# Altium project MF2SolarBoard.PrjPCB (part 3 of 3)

## Sheet Peripherals.SchDoc
size B; SheetNumber: 11; nhSheetName: Digital Peripherals
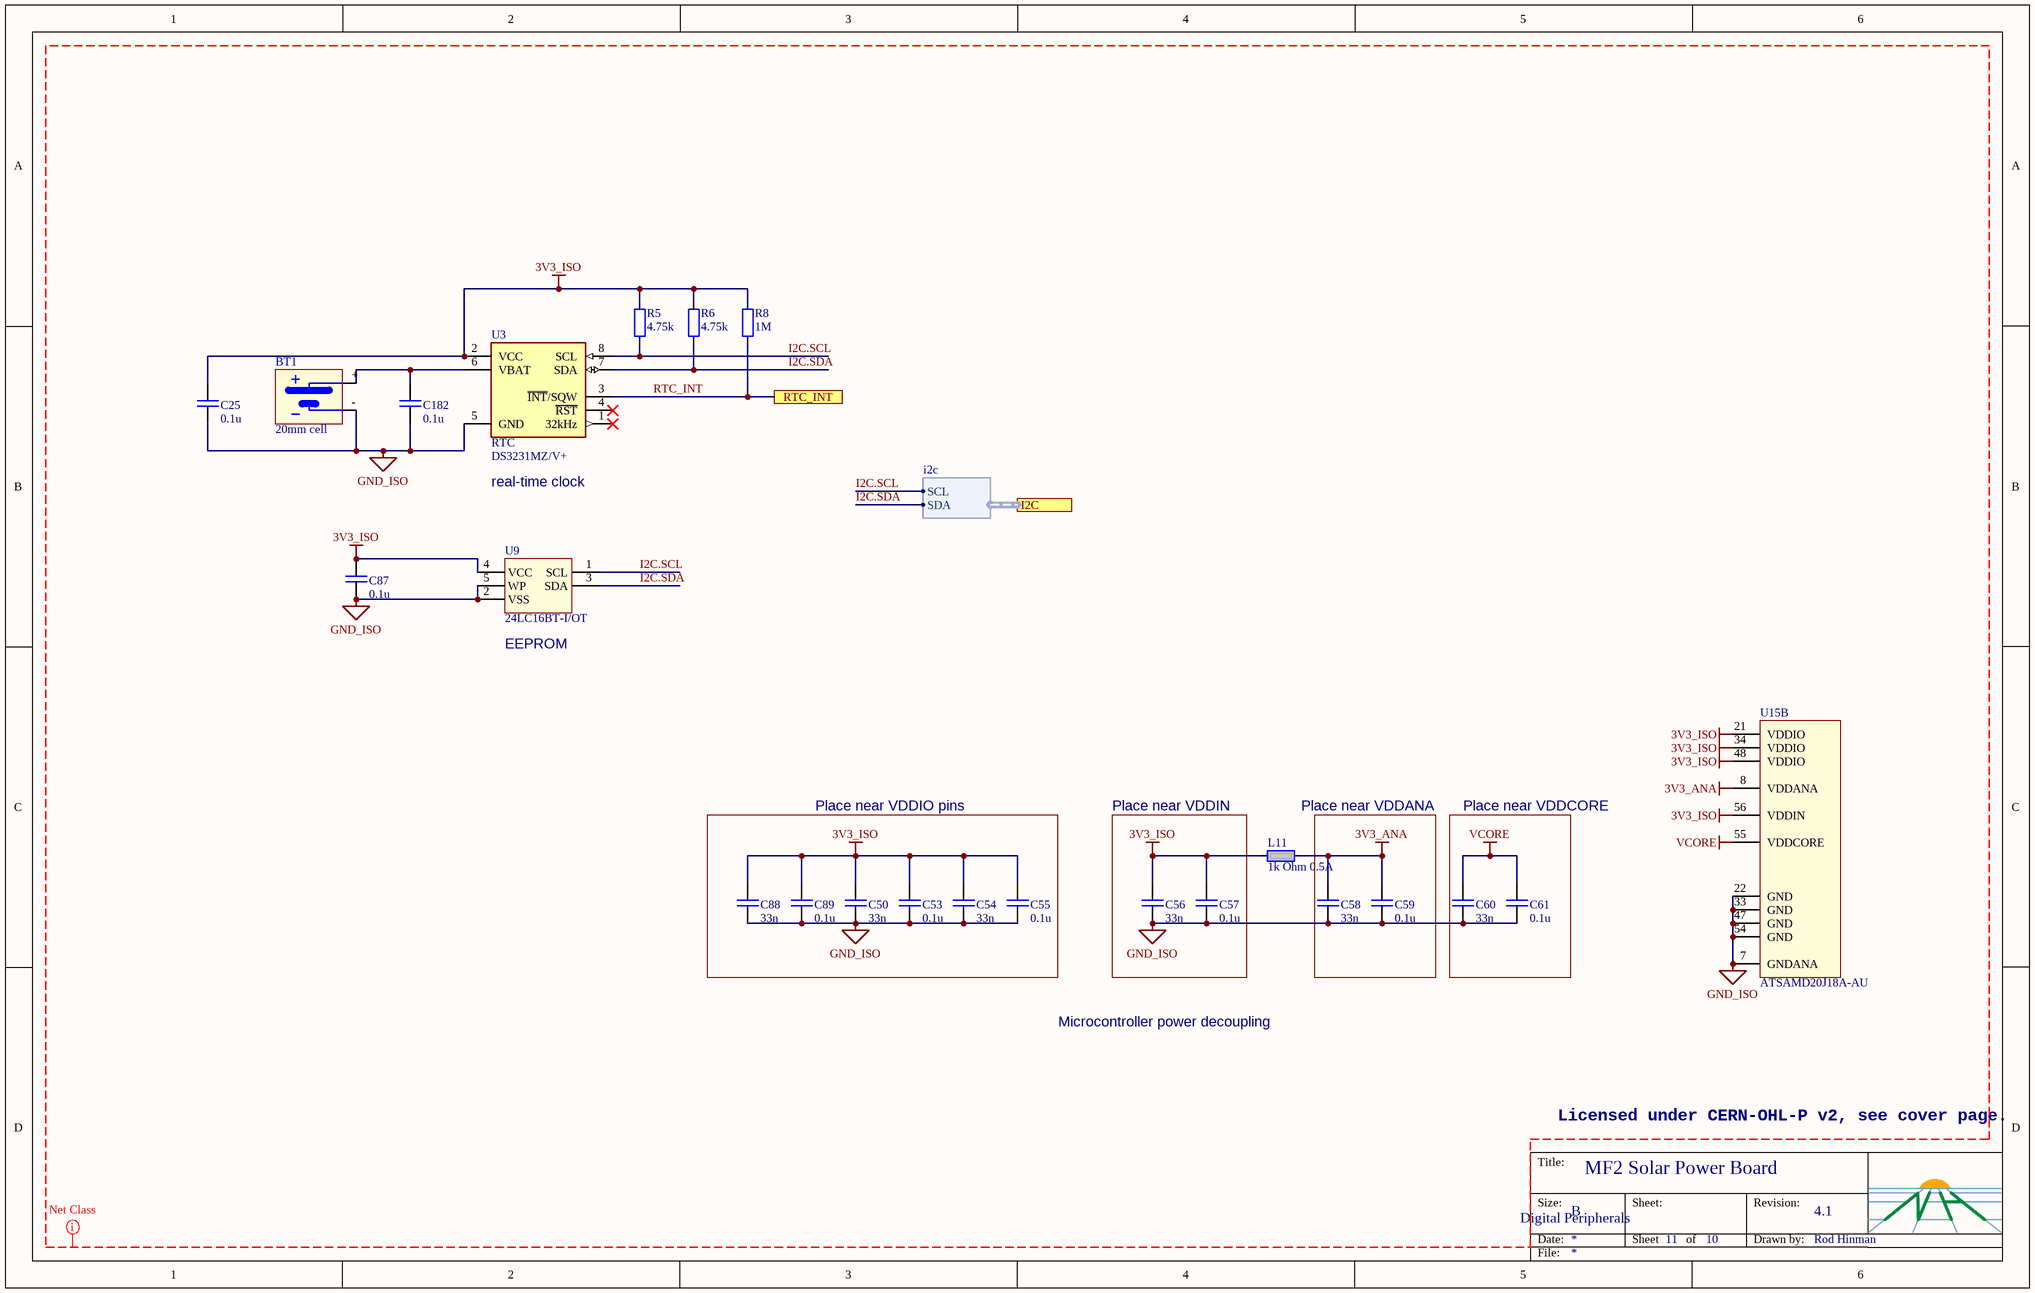
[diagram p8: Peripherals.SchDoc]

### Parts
BT1  20mm cell  [HARWIN_S8401-46]
C25  value_text: 0.1u  [CAPC1608X09N[0603]]  (hidden comment: 50V X7R 0603)
C50  value_text: 33n  [CAPC1608X09N[0603]]  (hidden comment: 50V X7R 0603)
C53  value_text: 0.1u  [CAPC1608X09N[0603]]  (hidden comment: 50V X7R 0603)
C54  value_text: 33n  [CAPC1608X09N[0603]]  (hidden comment: 50V X7R 0603)
C55  value_text: 0.1u  [CAPC1608X09N[0603]]  (hidden comment: 50V X7R 0603)
C56  value_text: 33n  [CAPC1608X09N[0603]]  (hidden comment: 50V X7R 0603)
C57  value_text: 0.1u  [CAPC1608X09N[0603]]  (hidden comment: 50V X7R 0603)
C58  value_text: 33n  [CAPC1608X09N[0603]]  (hidden comment: 50V X7R 0603)
C59  value_text: 0.1u  [CAPC1608X09N[0603]]  (hidden comment: 50V X7R 0603)
C60  value_text: 33n  [CAPC1608X09N[0603]]  (hidden comment: 50V X7R 0603)
C61  value_text: 0.1u  [CAPC1608X09N[0603]]  (hidden comment: 50V X7R 0603)
C87  value_text: 0.1u  [CAPC1608X09N[0603]]  (hidden comment: 50V X7R 0603)
C88  value_text: 33n  [CAPC1608X09N[0603]]  (hidden comment: 50V X7R 0603)
C89  value_text: 0.1u  [CAPC1608X09N[0603]]  (hidden comment: 50V X7R 0603)
C182  value_text: 0.1u  [CAPC1608X09N[0603]]  (hidden comment: 50V X7R 0603)
L11  1k Ohm 0.5A  [INDC2012X110N[0805]]
R5  value_text: 4.75k  [RESC1608X05AN[0603]]  (hidden comment: 1/10W 0603 1%)
R6  value_text: 4.75k  [RESC1608X05AN[0603]]  (hidden comment: 1/10W 0603 1%)
R8  value_text: 1M  [RESC1608X05AN[0603]]  (hidden comment: 1/10W 0603 1%)
U3  RTC  [SOIC127P600X170-8N]
U9  manufacturer_pn: 24LC16BT-I/OT  [SOT-23-5_MC]  (hidden comment: 16kbit I2C)
U15  manufacturer_pn: ATSAMD20J18A-AU  [ATM-TQFP64]  (hidden comment: 48MHz 256k 32k)  (part B of 2)

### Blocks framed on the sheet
Place near VDDIO pins: C50 C53-C55 C88 C89
Place near VDDIN: C56 C57
Place near VDDCORE: C60 C61

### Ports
I2C (harness i2c), RTC_INT

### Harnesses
i2c: SDA, SCL

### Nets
3V3_ANA: C58.1 C59.1 L11.2 U15.8(VDDANA)
3V3_ISO: C25.1 C50.1 C53.1 C54.1 C55.1 C56.1 C57.1 C87.1 C88.1 C89.1 L11.1 R5.2 R6.2 R8.2 U3.2(VCC) U9.4(VCC) U15.21(VDDIO) U15.34(VDDIO) U15.48(VDDIO) U15.56(VDDIN)
GND_ISO: BT1.- C25.2 C50.2 C53.2 C54.2 C55.2 C56.2 C57.2 C58.2 C59.2 C60.2 C61.2 C87.2 C88.2 C89.2 C182.2 U3.5(GND) U9.2(VSS) U9.5(WP) U15.7(GNDANA) U15.22(GND) U15.33(GND) U15.47(GND) U15.54(GND)
VCORE: C60.1 C61.1 U15.55(VDDCORE)
I2C.SCL: R5.1 U3.8(SCL) U9.1(SCL) ; port I2C.SCL
I2C.SDA: R6.1 U3.7(SDA) U9.3(SDA) ; port I2C.SDA
RTC_INT: R8.1 U3.3(~{INT}/SQW) ; port RTC_INT
NetBT1_+: BT1.+ C182.1 U3.6(VBAT)

Not connected (* = marked no-connect by the designer): U3 1(32kHz)* 4(~{RST})*

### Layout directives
net class SELV: 3V3_ANA, 3V3_ISO, GND_ISO, I2C.SCL, I2C.SDA, RTC_INT, VCORE

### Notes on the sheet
- real-time clock
- (near U9) EEPROM
- (near L11) Place near VDDANA
- Microcontroller power decoupling
- Licensed under CERN-OHL-P v2, see cover page.

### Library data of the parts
BT1 = CONN-00070: HOLDER BATT COIN CR2032/20MM; manufacturer: Harwin Inc.; manufacturer_pn: S8401-46; id: 140463
C25 C53 C55 C57 C59 C61 C87 C89 C182 = CAP-00001: 0.10µF 50V Ceramic Capacitor X7R 0603 (1608 Metric) 0.063" L x 0.031" W (1.60mm x 0.80mm); manufacturer: Murata Electronics North America; manufacturer_pn: GRM188R71H104KA93D; id: 136482; value: 1E-7; Key Parameters: V >= 25V
C50 C54 C56 C58 C60 C88 = CAP-00000: 0.033µF 50V Ceramic Capacitor X7R 0603 (1608 Metric) 0.063" L x 0.031" W (1.60mm x 0.80mm); manufacturer: Murata Electronics North America; manufacturer_pn: GRM188R71H333KA61D; id: 136460; value: 3.3E-8; Key Parameters: V >= 16V
L11 = FER-00005: FERRITE BEAD 1 KOHM 0805 1LN 0.28 ohm; manufacturer: Murata Electronics North America; manufacturer_pn: BLM21AG102SN1D; id: 137114; value: 1000
R5 R6 = RES-00013: RES SMD 4.75K OHM 1% 1/10W 0603; manufacturer: Panasonic Electronic Components; manufacturer_pn: ERJ-3EKF4751V; id: 137091; value: 4750; Key Parameters: 5% OK
R8 = RES-00114: 1 MOhms ±1% 0.1W, 1/10W Chip Resistor 0603 (1608 Metric) Automotive AEC-Q200 Thick Film; manufacturer: Panasonic Electronic Components; manufacturer_pn: ERJ-3EKF1004V; id: 185423; value: 1000000; Key Parameters: 5% OK
U3 = ICDIG-00002: Real Time Clock (RTC) IC Clock/Calendar I²C, 2-Wire Serial 8-SOIC (0.154in 3.90mm Width); manufacturer: Maxim Integrated; id: 137384
U9 = ICDIG-00007: EEPROM Memory IC 16Kb (2K x 8) I²C 900ns SOT-23-5; manufacturer: Microchip Technology; id: 169358
U15 = MCU-00010: ARM® Cortex®-M0+ SAM D20J Microcontroller IC 32-Bit 48MHz 256KB (256K x 8) FLASH 64-LQFP (10x10); manufacturer: Atmel; id: 169288

## Sheet HVAuxOutput.SchDoc
size B; SheetNumber: 8; nhSheetName: HV Auxiliary Output
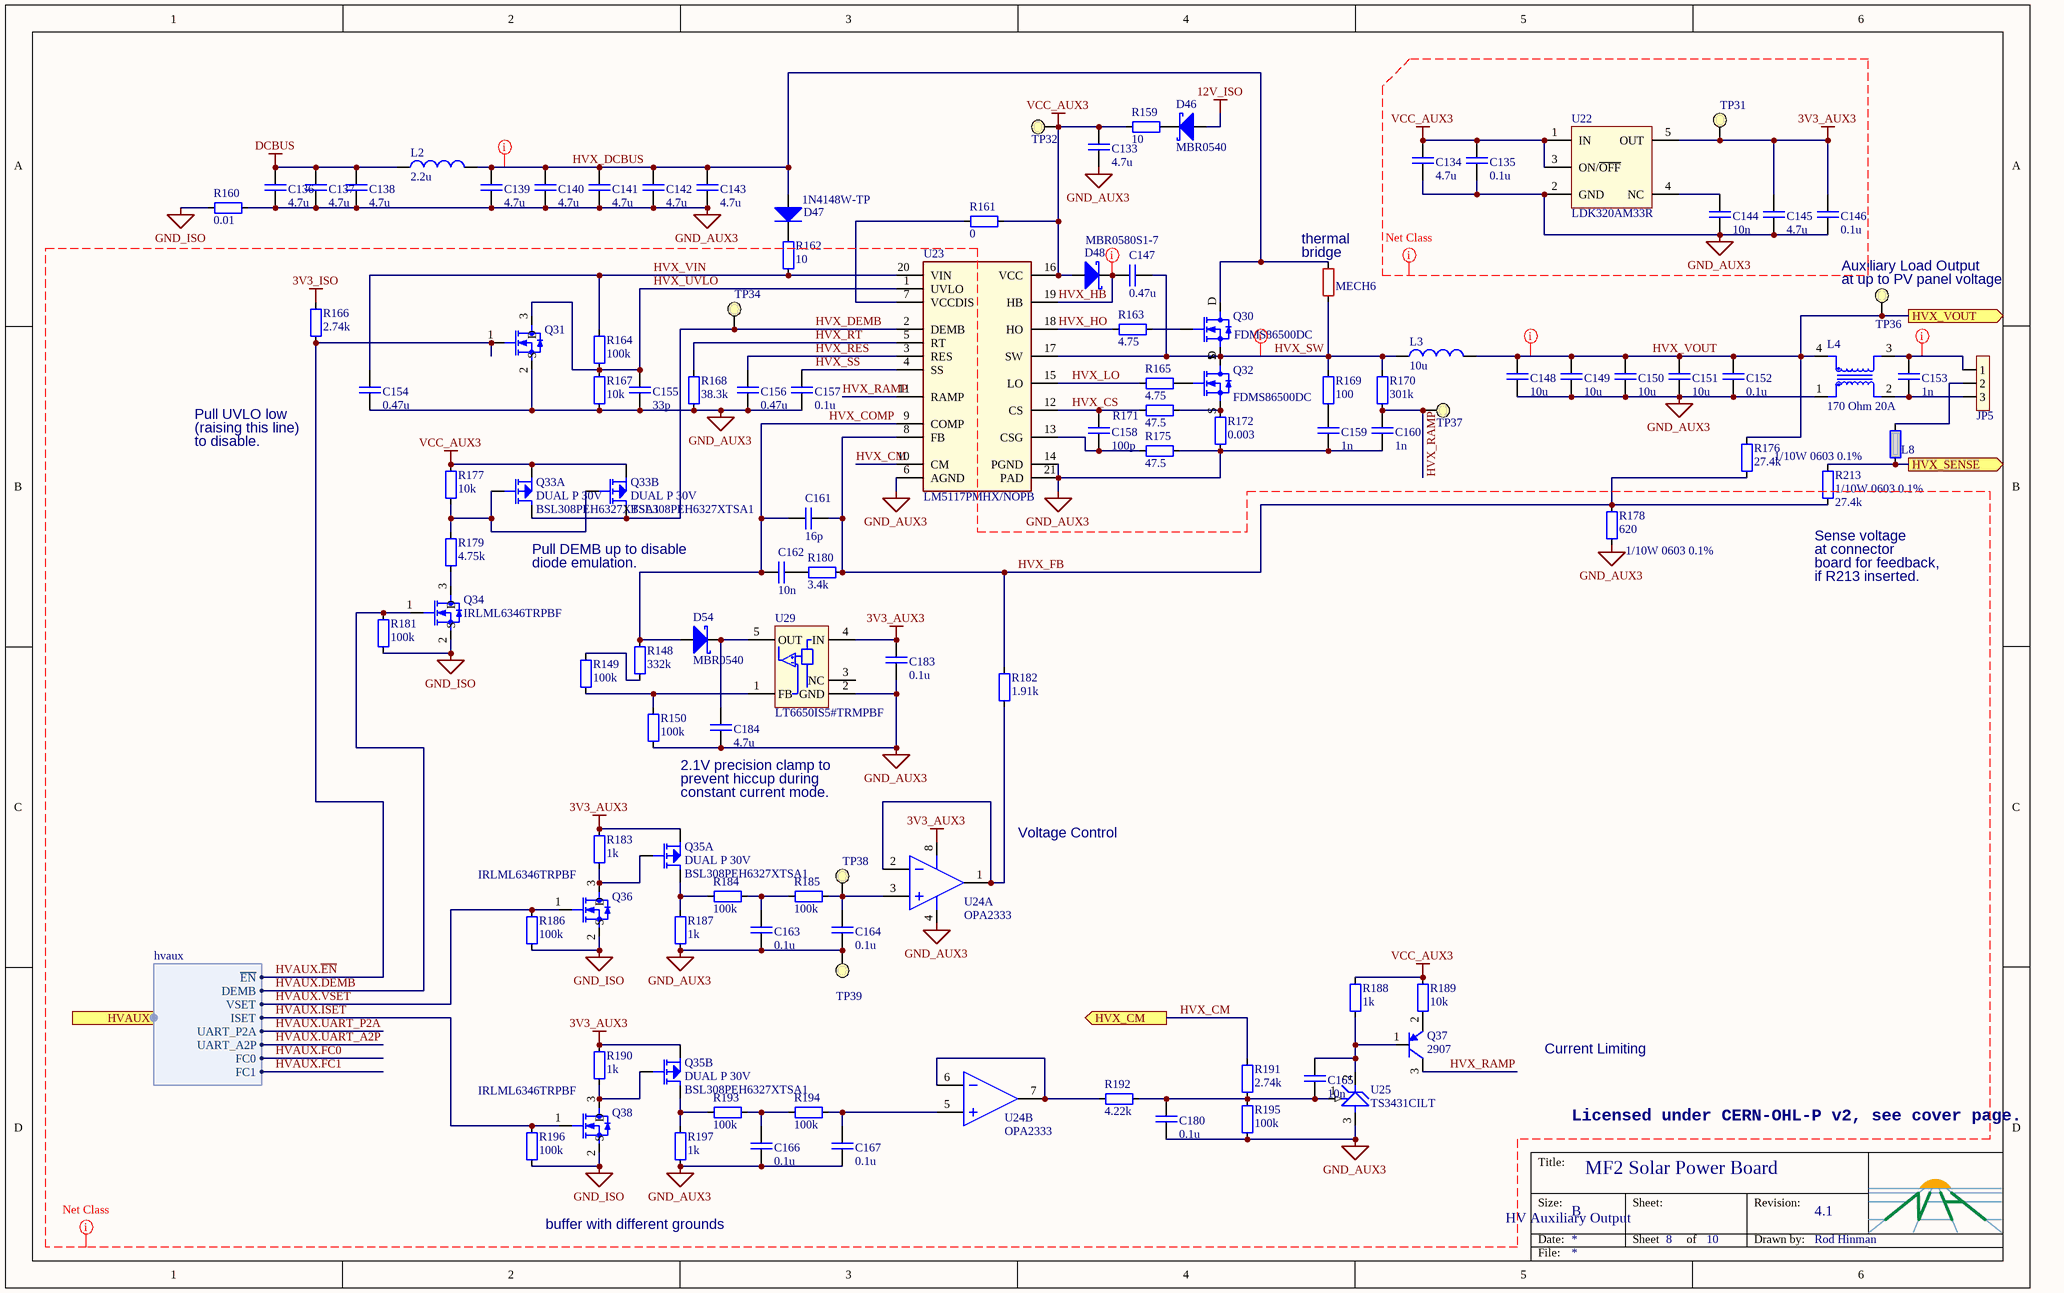
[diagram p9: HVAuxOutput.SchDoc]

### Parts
C133  value_text: 4.7u  [CAPC1608X09N[0603]]  (hidden comment: 25V X6S 0603)
C134  value_text: 4.7u  [CAPC1608X09N[0603]]  (hidden comment: 25V X6S 0603)
C135  value_text: 0.1u  [CAPC1608X09N[0603]]  (hidden comment: 50V X7R 0603)
C136  value_text: 4.7u  [CAPC3225X270]  (hidden comment: 100V X5R 1210)
C137  value_text: 4.7u  [CAPC3225X270]  (hidden comment: 100V X5R 1210)
C138  value_text: 4.7u  [CAPC3225X270]  (hidden comment: 100V X5R 1210)
C139  value_text: 4.7u  [CAPC3225X270]  (hidden comment: 100V X5R 1210)
C140  value_text: 4.7u  [CAPC3225X270]  (hidden comment: 100V X5R 1210)
C141  value_text: 4.7u  [CAPC3225X270]  (hidden comment: 100V X5R 1210)
C142  value_text: 4.7u  [CAPC3225X270]  (hidden comment: 100V X5R 1210)
C143  value_text: 4.7u  [CAPC3225X270]  (hidden comment: 100V X5R 1210)
C144  value_text: 10n  [CAPC1608X09N[0603]]  (hidden comment: 50V C0G 0603)
C145  value_text: 4.7u  [CAPC1608X09N[0603]]  (hidden comment: 25V X6S 0603)
C146  value_text: 0.1u  [CAPC1608X09N[0603]]  (hidden comment: 50V X7R 0603)
C147  value_text: 0.47u  [CAPC2012X135]  (hidden comment: 100V X7S 0805)
C148  value_text: 10u  [CAPC3216X180]  (hidden comment: 50V X5R 1206)
C149  value_text: 10u  [CAPC3216X180]  (hidden comment: 50V X5R 1206)
C150  value_text: 10u  [CAPC3216X180]  (hidden comment: 50V X5R 1206)
C151  value_text: 10u  [CAPC3216X180]  (hidden comment: 50V X5R 1206)
C152  value_text: 0.1u  [CAPC1608X09N[0603]]  (hidden comment: 50V X7R 0603)
C153  value_text: 1n  [CAPC1608X09N[0603]]  (hidden comment: 50V C0G 0603)
C154  value_text: 0.47u  [CAPC2012X135]  (hidden comment: 100V X7S 0805)
C155  value_text: 33p  [CAPC1608X09N[0603]]  (hidden comment: 50V C0G 0603)
C156  value_text: 0.47u  [CAPC2012X135]  (hidden comment: 100V X7S 0805)
C157  value_text: 0.1u  [CAPC1608X09N[0603]]  (hidden comment: 50V X7R 0603)
C158  value_text: 100p  [CAPC1608X09N[0603]]  (hidden comment: 50V C0G 0603)
C159  value_text: 1n  [CAPC1608X09N[0603]]  (hidden comment: 50V C0G 0603)
C160  value_text: 1n  [CAPC1608X09N[0603]]  (hidden comment: 50V C0G 0603)
C161  value_text: 16p  [CAPC1608X09N[0603]]  (hidden comment: 50V C0G 0603)
C162  value_text: 10n  [CAPC1608X09N[0603]]  (hidden comment: 50V C0G 0603)
C163  value_text: 0.1u  [CAPC1608X09N[0603]]  (hidden comment: 50V X7R 0603)
C164  value_text: 0.1u  [CAPC1608X09N[0603]]  (hidden comment: 50V X7R 0603)
C165  value_text: 10n  [CAPC1608X09N[0603]]  (hidden comment: 50V C0G 0603)
C166  value_text: 0.1u  [CAPC1608X09N[0603]]  (hidden comment: 50V X7R 0603)
C167  value_text: 0.1u  [CAPC1608X09N[0603]]  (hidden comment: 50V X7R 0603)
C180  value_text: 0.1u  [CAPC1608X09N[0603]]  (hidden comment: 50V X7R 0603)
C183  value_text: 0.1u  [CAPC1608X09N[0603]]  (hidden comment: 50V X7R 0603)
C184  value_text: 4.7u  [CAPC1608X09N[0603]]  (hidden comment: 25V X6S 0603)
D46  manufacturer_pn: MBR0540  [SOD-123]  (hidden comment: 40V 500mA)
D47  manufacturer_pn: 1N4148W-TP  [SOD-123]  (hidden comment: 1N4148)
D48  manufacturer_pn: MBR0580S1-7  [SOD-123]  (hidden comment: 80V 500mA)
D54  manufacturer_pn: MBR0540  [SOD-123]  (hidden comment: 40V 500mA)
JP5  JST VL  [JST_B03P-VL]  (value not drawn)
L2  value_text: 2.2u  [INDUCTOR-BOURNS_SRP1270]  (hidden comment: 22A 4mOhm)
L3  value_text: 10u  [INDUCTOR_VISHAY_IHLP-6767]  (hidden comment: 19A 9mOhm)
L4  170 Ohm 20A  [LAIRD_CM3443Z171R-10]
L8  1k Ohm 0.5A  [INDC2012X110N[0805]]  (value not drawn)
MECH6  10C/W  [RESC2012X06N[0805]]  (value not drawn)
Q30  manufacturer_pn: FDMS86500DC  [SOIC-8 PPAK]  (hidden comment: N-CH 60V 29A)
Q31  N-CH 30V 3.4A  [SOT23-3]  (value not drawn)
Q32  manufacturer_pn: FDMS86500DC  [SOIC-8 PPAK]  (hidden comment: N-CH 60V 29A)
Q33  DUAL P 30V  manufacturer_pn: BSL308PEH6327XTSA1  [SOT_23_6]  (parts A,B of 2)
Q34  manufacturer_pn: IRLML6346TRPBF  [SOT23-3]  (hidden comment: N-CH 30V 3.4A)
Q35  DUAL P 30V  manufacturer_pn: BSL308PEH6327XTSA1  [SOT_23_6]  (parts A,B of 2)
Q36  manufacturer_pn: IRLML6346TRPBF  [SOT23-3]  (hidden comment: N-CH 30V 3.4A)
Q37  2907  [SOT23-3]
Q38  manufacturer_pn: IRLML6346TRPBF  [SOT23-3]  (hidden comment: N-CH 30V 3.4A)
R148  value_text: 332k  [RESC1608X05AN[0603]]  (hidden comment: 1/10W 0603 1%)
R149  value_text: 100k  [RESC1608X05AN[0603]]  (hidden comment: 1/10W 0603 1%)
R150  value_text: 100k  [RESC1608X05AN[0603]]  (hidden comment: 1/10W 0603 1%)
R159  value_text: 10  [RESC1608X05AN[0603]]  (hidden comment: 1/10W 0603 pulse)
R160  value_text: 0.01  [RESC6534X70[2512]]  (hidden comment: 3W 2512 1%)
R161  value_text: 0  [RESC1608X05AN[0603]]  (hidden comment: 1/10W 0603 Jumper)
R162  value_text: 10  [RESC1608X05AN[0603]]  (hidden comment: 1/10W 0603 pulse)
R163  value_text: 4.75  [RESC1608X05AN[0603]]  (hidden comment: 1/10W 0603 1%)
R164  value_text: 100k  [RESC1608X05AN[0603]]  (hidden comment: 1/10W 0603 1%)
R165  value_text: 4.75  [RESC1608X05AN[0603]]  (hidden comment: 1/10W 0603 1%)
R166  value_text: 2.74k  [RESC1608X05AN[0603]]  (hidden comment: 1/10W 0603 1%)
R167  value_text: 10k  [RESC1608X05AN[0603]]  (hidden comment: 1/10W 0603 1%)
R168  value_text: 38.3k  [RESC1608X05AN[0603]]  (hidden comment: 1/10W 0603)
R169  value_text: 100  [RESC6534X70[2512]]  (hidden comment: 1W 2512 5%)
R170  value_text: 301k  [RESC1608X05AN[0603]]  (hidden comment: 1/10W 0603)
R171  value_text: 47.5  [RESC1608X05AN[0603]]  (hidden comment: 1/10W 0603 1%)
R172  value_text: 0.003  [RESC6534X70[2512]]  (hidden comment: 3W 2512 1%)
R175  value_text: 47.5  [RESC1608X05AN[0603]]  (hidden comment: 1/10W 0603 1%)
R176  1/10W 0603 0.1%  value_text: 27.4k  [RESC1608X05AN[0603]]
R177  value_text: 10k  [RESC1608X05AN[0603]]  (hidden comment: 1/10W 0603 1%)
R178  1/10W 0603 0.1%  value_text: 620  [RESC1608X05AN[0603]]
R179  value_text: 4.75k  [RESC1608X05AN[0603]]  (hidden comment: 1/10W 0603 1%)
R180  value_text: 3.4k  [RESC1608X05AN[0603]]  (hidden comment: 1/10W 0603 0.1%)
R181  value_text: 100k  [RESC1608X05AN[0603]]  (hidden comment: 1/10W 0603 1%)
R182  value_text: 1.91k  [RESC1608X05AN[0603]]  (hidden comment: 1/10W 0603 0.1%)
R183  value_text: 1k  [RESC1608X05AN[0603]]  (hidden comment: 1/10W 0603 1%)
R184  value_text: 100k  [RESC1608X05AN[0603]]  (hidden comment: 1/10W 0603 1%)
R185  value_text: 100k  [RESC1608X05AN[0603]]  (hidden comment: 1/10W 0603 1%)
R186  value_text: 100k  [RESC1608X05AN[0603]]  (hidden comment: 1/10W 0603 1%)
R187  value_text: 1k  [RESC1608X05AN[0603]]  (hidden comment: 1/10W 0603 1%)
R188  value_text: 1k  [RESC1608X05AN[0603]]  (hidden comment: 1/10W 0603 1%)
R189  value_text: 10k  [RESC1608X05AN[0603]]  (hidden comment: 1/10W 0603 1%)
R190  value_text: 1k  [RESC1608X05AN[0603]]  (hidden comment: 1/10W 0603 1%)
R191  value_text: 2.74k  [RESC1608X05AN[0603]]  (hidden comment: 1/10W 0603 1%)
R192  value_text: 4.22k  [RESC1608X05AN[0603]]  (hidden comment: 1/10W 0603 0.1%)
R193  value_text: 100k  [RESC1608X05AN[0603]]  (hidden comment: 1/10W 0603 1%)
R194  value_text: 100k  [RESC1608X05AN[0603]]  (hidden comment: 1/10W 0603 1%)
R195  value_text: 100k  [RESC1608X05AN[0603]]  (hidden comment: 1/10W 0603 1%)
R196  value_text: 100k  [RESC1608X05AN[0603]]  (hidden comment: 1/10W 0603 1%)
R197  value_text: 1k  [RESC1608X05AN[0603]]  (hidden comment: 1/10W 0603 1%)
R213  1/10W 0603 0.1%  value_text: 27.4k  [RESC1608X05AN[0603]]
TP31  TP SMD 1.5mm  [TP_SMD_Ø1.5mm]  (value not drawn)  (no BOM)
TP32  TP SMD 1.5mm  [TP_SMD_Ø1.5mm]  (value not drawn)  (no BOM)
TP34  TP SMD 1.5mm  [TP_SMD_Ø1.5mm]  (value not drawn)  (no BOM)
TP36  TP SMD 1.5mm  [TP_SMD_Ø1.5mm]  (value not drawn)  (no BOM)
TP37  TP SMD 1.5mm  [TP_SMD_Ø1.5mm]  (value not drawn)  (no BOM)
TP38  TP SMD 1.5mm  [TP_SMD_Ø1.5mm]  (value not drawn)  (no BOM)
TP39  TP SMD 1.5mm  [TP_SMD_Ø1.5mm]  (value not drawn)  (no BOM)
U22  manufacturer_pn: LDK320AM33R  [TI-SOT-23-5_MC]  (hidden comment: 3.3V 200mA)
U23  manufacturer_pn: LM5117PMHX/NOPB  [TSOP65P640X110_HS-21N]  (hidden comment: LM5117)
U24  OPA2333  [MSOP-8]  (parts A,B of 2)
U25  manufacturer_pn: TS3431CILT  [SOT_23_3]  (hidden comment: TS3431)
U29  manufacturer_pn: LT6650IS5#TRMPBF  [SOT-23-5]  (hidden comment: LT6650)

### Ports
HVAUX (harness hvaux), HVX_CM (out), HVX_SENSE (out), HVX_VOUT (out)

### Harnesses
hvaux: ~{EN}, VSET, UART_P2A, UART_A2P, FC0, FC1, ISET, DEMB

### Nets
3V3_AUX3: C145.1 C146.1 C183.1 Q35.2(S2) Q35.5(S1) R183.2 R190.1 TP31.1 U22.5(OUT) U24.8(V+) U29.4(IN)
3V3_ISO: R166.2
12V_ISO: D46.A
DCBUS: C136.1 C137.1 C138.1 L2.1
GND_AUX3: C133.2 C134.2 C135.2 C136.2 C137.2 C138.2 C139.2 C140.2 C141.2 C142.2 C143.2 C144.2 C145.2 C146.2 C148.2 C149.2 C150.2 C151.2 C152.2 C154.2 C155.2 C156.2 C157.2 C159.2 C160.2 C163.2 C164.2 C166.2 C167.2 C180.2 C183.2 C184.2 L4.1 Q31.2(S) R150.2 R160.2 R167.2 R168.2 R172.2 R175.2 R178.2 R187.2 R195.2 R197.2 TP39.1 U22.2(GND) U23.6(AGND) U23.14(PGND) U23.21(PAD) U24.4(V-) U25.3(A) U29.2(GND)
GND_ISO: Q34.2(S) Q36.2(S) Q38.2(S) R160.1 R181.1 R186.1 R196.1
VCC_AUX3: C133.1 C134.1 C135.1 D48.A Q33.2(S2) Q33.5(S1) R159.2 R161.2 R177.2 R188.2 R189.2 TP32.1 U22.1(IN) U22.3(ON/~{OFF}) U23.16(VCC)
HVAUX.DEMB: Q34.1(G) R181.2 ; port HVAUX.DEMB
HVAUX.~{EN}: Q31.1(G) R166.1 ; port HVAUX.~{EN}
HVAUX.ISET: Q38.1(G) R196.2 ; port HVAUX.ISET
HVAUX.VSET: Q36.1(G) R186.2 ; port HVAUX.VSET
HVX_CM: R191.1 U23.10(CM) ; port HVX_CM
HVX_COMP: C161.2 C162.2 D54.A R148.1 U23.9(COMP)
HVX_CS: C158.1 R171.1 U23.12(CS)
HVX_DCBUS: C139.1 C140.1 C141.1 C142.1 C143.1 D47.A L2.2 MECH6.2 Q30.D
HVX_DEMB: Q33.4(D2) Q33.6(D1) TP34.1 U23.2(DEMB)
HVX_FB: C161.1 R176.2 R178.1 R180.1 R182.1 R213.2 U23.8(FB)
HVX_HB: C147.1 D48.K U23.19(HB)
HVX_HO: R163.1 U23.18(HO)
HVX_LO: R165.1 U23.15(LO)
HVX_RAMP: C160.1 Q37.3(C) R170.2 TP37.1 U23.11(RAMP)
HVX_RES: C156.1 U23.3(RES)
HVX_RT: R168.1 U23.5(RT)
HVX_SS: C157.1 U23.4(SS)
HVX_SW: C147.2 L3.1 MECH6.1 Q30.S Q32.D R169.1 R170.1 U23.17(SW)
HVX_UVLO: C155.1 Q31.3(D) R164.2 R167.1 U23.1(UVLO)
HVX_VIN: C154.1 R162.2 R164.1 U23.20(VIN)
HVX_VOUT: C148.1 C149.1 C150.1 C151.1 C152.1 L3.2 L4.4 R176.1 TP36.1 ; port HVX_VOUT
NetC144_1: C144.1 U22.4(NC)
NetC153_1: C153.1 JP5.1 L4.3
NetC153_2: C153.2 JP5.3 L4.2
NetC158_2: C158.2 R175.1 U23.13(CSG)
NetC159_1: C159.1 R169.2
NetC162_1: C162.1 R180.2
NetC163_1: C163.1 R184.1 R185.2
NetC164_1: C164.1 R185.1 TP38.1 U24.3(IN+)
NetC165_1: C165.1 Q37.1(B) R188.1 U25.2(K)
NetC165_2: C165.2 C180.1 R191.2 R192.2 R195.1 U25.1(VREF)
NetC166_1: C166.1 R193.1 R194.2
NetC167_1: C167.1 R194.1 U24.5(IN+)
NetC184_1: C184.1 D54.K U29.5(OUT)
NetD46_K: D46.K R159.1
NetD47_K: D47.K R162.1
NetJP5_2: JP5.2 L8.2
NetL8_1: L8.1 R213.1 ; port HVX_SENSE
NetQ30_G: Q30.G R163.2
NetQ32_G: Q32.G R165.2
NetQ32_S: Q32.S R171.2 R172.1
NetQ33_1: Q33.1(G1) Q33.3(G2) R177.1 R179.1
NetQ34_3: Q34.3(D) R179.2
NetQ35_1: Q35.1(G1) Q36.3(D) R183.1
NetQ35_3: Q35.3(G2) Q38.3(D) R190.2
NetQ35_4: Q35.4(D2) R193.2 R197.1
NetQ35_6: Q35.6(D1) R184.2 R187.1
NetQ37_2: Q37.2(E) R189.1
NetR148_2: R148.2 R149.1
NetR149_2: R149.2 R150.1 U29.1(FB)
NetR161_1: R161.1 U23.7(VCCDIS)
NetR182_2: R182.2 U24.1(OUT) U24.2(IN-)
NetR192_1: R192.1 U24.6(IN-) U24.7(OUT)

Not connected (* = marked no-connect by the designer): U29 3(NC)

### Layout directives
net class SELV: 3V3_AUX3, 3V3_ISO, GND_AUX3, GND_ISO, HVAUX.DEMB, HVAUX.FC0, HVAUX.FC1, HVAUX.ISET, HVAUX.UART_A2P, HVAUX.UART_P2A, HVAUX.VSET, HVAUX.~{EN}, HVX_CM, HVX_COMP, HVX_CS, HVX_DEMB, HVX_FB, HVX_HB, HVX_HO, HVX_LO, HVX_RAMP, HVX_RES, HVX_RT, HVX_SS, HVX_SW, HVX_UVLO, HVX_VIN, HVX_VOUT, VCC_AUX3
net class PVPOS: HVX_DCBUS, HVX_HB, HVX_SW, HVX_VOUT, NetC153_1

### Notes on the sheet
- (near MECH6) thermal
- (near MECH6) bridge
- Auxiliary Load Output
- (near TP36) at up to PV panel voltage
- Pull UVLO low
- (near C154) (raising this line)
- to disable.
- (near Q33) Pull DEMB up to disable
- (near Q33) diode emulation.
- (near R213) Sense voltage
- (near R213) at connector
- board for feedback,
- if R213 inserted.
- 2.1V precision clamp to
- prevent hiccup during
- constant current mode.
- Voltage Control
- Current Limiting
- Licensed under CERN-OHL-P v2, see cover page.
- buffer with different grounds

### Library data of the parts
C133 C134 C145 C184 = CAP-00015: 4.7µF 25V Ceramic Capacitor X6S 0603 (1608 Metric) 0.063" L x 0.031" W (1.60mm x 0.80mm); manufacturer: Murata Electronics North America; manufacturer_pn: GRM188C81E475KE11D; id: 136726; value: 4.7E-6; Key Parameters: V >= 16V
C135 C146 C152 C157 C163 C164 C166 C167 C180 C183 = CAP-00001: as C25 on sheet Peripherals
C136-C143 = CAP-00075: 4.7µF ±10% 100V Ceramic Capacitor X5R 1210 (3225 Metric); manufacturer: Taiyo Yuden; manufacturer_pn: HMK325BJ475KM-PE; id: 171762; value: 4.7E-6; Key Parameters: V >= 50V preferred, 25V possible
C144 C162 C165 = CAP-00027: 10000pF 50V Ceramic Capacitor C0G, NP0 0603 (1608 Metric) 0.063" L x 0.031" W (1.60mm x 0.80mm); manufacturer: Murata Electronics North America; manufacturer_pn: GRM1885C1H103JA01D; id: 137118; value: 1E-8; Key Parameters: V >= 6.3V
C147 C154 C156 = CAP-00076: 0.47µF ±10% 100V Ceramic Capacitor X7S 0805 (2012 Metric); manufacturer: Taiyo Yuden; manufacturer_pn: HMK212C7474KGHTE; id: 171763; value: 4.7E-7; Key Parameters: V >= 50V preferred, 25V possible
C148-C151 = CAP-00074: 10µF ±20% 50V Ceramic Capacitor X5R 1206 (3216 Metric); manufacturer: TDK Corporation; manufacturer_pn: C3216X5R1H106M160AB; id: 171760; value: 1E-5; Key Parameters: V >= 50V preferred, V >= 25 OK.
C153 C159 C160 = CAP-00053: 1000pF ±5% 50V Ceramic Capacitor C0G, NP0 0603 (1608 Metric); manufacturer: Murata Electronics North America; manufacturer_pn: GRM1885C1H102JA01D; id: 147791; value: 1E-9; Key Parameters: V >= 25V
C155 = CAP-00043: 33pF 50V Ceramic Capacitor C0G, NP0 0603 (1608 Metric) 0.063" L x 0.031" W (1.60mm x 0.80mm); manufacturer: Murata Electronics North America; manufacturer_pn: GRM1885C1H330JA01D; id: 140735; value: 3.3E-11; Key Parameters: v >= 6.3V
C158 = CAP-00078: 100pF ±5% 50V Ceramic Capacitor C0G, NP0 0603 (1608 Metric); manufacturer: Murata Electronics North America; manufacturer_pn: GRM1885C1H101JA01D; id: 178863; value: 1E-10; Key Parameters: V >= 6.3V
C161 = CAP-00051: 16pF ±5% 50V Ceramic Capacitor C0G, NP0 0603 (1608 Metric); manufacturer: Murata Electronics North America; manufacturer_pn: GRM1885C1H160JA01D; id: 147785; value: 1.6E-11; Key Parameters: V >= 16V
D46 D54 = DIO-00007: Diode Schottky 40V 500mA Surface Mount SOD-123; manufacturer: Fairchild Semiconductor; id: 137137
D47 = DIO-00004: Diode Standard 100V 150mA Surface Mount SOD-123; manufacturer: Micro Commercial Co; id: 137134
D48 = DIO-00030: Diode Schottky 80V 500mA Surface Mount SOD-123; manufacturer: Diodes Incorporated; id: 171756
JP5 = CONN-00119: 3 Positions Header Connector 0.244" (6.20mm) Through Hole Tin; manufacturer: JST Sales America Inc.; manufacturer_pn: B03P-VL; id: 170440
L2 = IND-00024: 2.2uH Shielded Wirewound Inductor 22A 4.2 mOhm Max Nonstandard; manufacturer_pn: SRP1270-2R2M; manufacturer: Bourns Inc.; id: 171912; value: 2.2E-6
L3 = IND-00025: 10uH Shielded Molded Inductor 19A 9.33 mOhm Max Nonstandard; manufacturer_pn: IHLP6767GZER100M11; manufacturer: Vishay Dale; id: 171915; value: 1E-5
L4 = FER-00010: 2 Line Common Mode Choke Surface Mount 170 Ohm @ 100MHz 20A DCR 1 mOhm; manufacturer: Laird Technologies EMI; manufacturer_pn: CM3440Z171R-10; value_text: 170; id: 169934; value: 170
L8 = FER-00005: FERRITE BEAD 1 KOHM 0805 1LN 0.28 ohm; manufacturer_pn: BLM21AG102SN1D; manufacturer: Murata Electronics North America; id: 137114; value: 1000
MECH6 = MECH-00031: Heat Sink Aluminum Nitride Ceramic Heat Spreader Q-Bridge; manufacturer_pn: QB0805A40WYTD; manufacturer: American Technical Ceramics; id: 197164
Q30 Q32 = FET-00018: N-Channel 60V 29A (Ta), 108A (Tc) 3.2W (Ta), 125W (Tc) Surface Mount Dual Cool™56; manufacturer: ON Semiconductor; id: 193254
Q31 = FET-00002: MOSFET N-CH 30V 3.4A SOT23; manufacturer_pn: IRLML6346TRPBF; manufacturer: Infineon Technologies; id: 137229
Q33 Q35 = FET-00023: Mosfet Array 2 P-Channel (Dual) 30V 2A 500mW Surface Mount PG-TSOP-6-6; manufacturer: Infineon Technologies; id: 297421
Q34 Q36 Q38 = FET-00002: MOSFET N-CH 30V 3.4A SOT23; manufacturer: Infineon Technologies; id: 137229
Q37 = BJT-00002: TRANS PNP 60V 0.6A SOT23; manufacturer_pn: MMBT2907ALT1G; manufacturer: ON Semiconductor; id: 172166
R148 = RES-00064: RES SMD 332K OHM 1% 1/10W 0603; manufacturer_pn: ERJ-3EKF3323V; manufacturer: Panasonic Electronic Components; id: 147650; value: 332000; Key Parameters: 1% required
R149 R150 R181 R184-R186 R193-R196 = RES-00112: 100 kOhms ±1% 0.1W, 1/10W Chip Resistor 0603 (1608 Metric) Automotive AEC-Q200 Thick Film; manufacturer: Panasonic Electronic Components; manufacturer_pn: ERJ-3EKF1003V; id: 185358; value: 100000; Key Parameters: 1% required
R159 R162 = RES-00100: 10 Ohm ±5% 0.25W, 1/4W Chip Resistor 0603 (1608 Metric) Automotive AEC-Q200, Pulse Withstanding Thick Film; manufacturer_pn: ESR03EZPF10R0; manufacturer: Rohm Semiconductor; id: 171757; value: 10; Key Parameters: 5% OK
R160 = RES-00036: RES SMD 0.01 OHM 1% 3W 2512; manufacturer_pn: CRA2512-FZ-R010ELF; manufacturer: Bourns Inc.; id: 137235; value: 0.01; Key Parameters: 1% required
R161 = RES-00010: RES SMD 0.0OHM JUMPER 1/10W 0603; manufacturer_pn: ERJ-3GEY0R00V; manufacturer: Panasonic Electronic Components; id: 137088; value: 0
R163 R165 = RES-00126: RES SMD 4.75 OHM 1% 1/10W 0603; manufacturer_pn: CRCW06034R75FKEA; manufacturer: Vishay Dale; id: 193543; value: 4.75; Key Parameters: 5% OK
R164 = RES-00112: 100 kOhms ±1% 0.1W, 1/10W Chip Resistor 0603 (1608 Metric) Automotive AEC-Q200 Thick Film; manufacturer_pn: ERJ-3EKF1003V; manufacturer: Panasonic Electronic Components; id: 185358; value: 100000; Key Parameters: 1% required
R166 = RES-00055: RES SMD 2.74K OHM 1% 1/10W 0603; manufacturer_pn: ERJ-3EKF2741V; manufacturer: Panasonic Electronic Components; id: 144315; value: 2740; Key Parameters: 1% required
R167 = RES-00107: 10 kOhms ±1% 0.1W, 1/10W Chip Resistor 0603 (1608 Metric) Automotive AEC-Q200 Thick Film; manufacturer_pn: ERJ-3EKF1002V; manufacturer: Panasonic Electronic Components; id: 182861; value: 10000; Key Parameters: 1% required
R168 = RES-00101: 38.3k Ohm ±1% 0.1W, 1/10W Chip Resistor 0603 (1608 Metric) Automotive AEC-Q200 Thick Film; manufacturer_pn: ERJ-3EKF3832V; manufacturer: Panasonic Electronic Components; id: 171758; value: 38300; Key Parameters: 1% required
R169 = RES-00098: RES SMD 100 OHM 5% 1W 2512; manufacturer_pn: ERJ-1TYJ101U; manufacturer: Panasonic Electronic Components; id: 171401; value: 100; Key Parameters: 5% OK
R170 = RES-00102: 301k Ohm ±1% 0.1W, 1/10W Chip Resistor 0603 (1608 Metric) Automotive AEC-Q200 Thick Film; manufacturer_pn: ERJ-3EKF3013V; manufacturer: Panasonic Electronic Components; id: 171759; value: 301000; Key Parameters: 1% required
R171 R175 = RES-00015: RES SMD 47.5 OHM 1% 1/10W 0603; manufacturer_pn: ERJ-3EKF47R5V; manufacturer: Panasonic Electronic Components; id: 137093; value: 47.5; Key Parameters: 1% required
R172 = RES-00105: 0.003 Ohm ±1% 3W Chip Resistor 2512 (6432 Metric) Automotive AEC-Q200, Current Sense, Moisture Resistant Metal Element; manufacturer_pn: CRE2512-FZ-R003E-3; manufacturer: Bourns Inc.; id: 172189; value: 0.003; Key Parameters: 1% required
R176 R213 = RES-00051: RES SMD 27.4KOHM 0.1% 1/10W 0603; manufacturer: Panasonic Electronic Components; manufacturer_pn: ERA-3AEB2742V; id: 141324; value: 27400; Key Parameters: 0.1% required
R177 R189 = RES-00107: 10 kOhms ±1% 0.1W, 1/10W Chip Resistor 0603 (1608 Metric) Automotive AEC-Q200 Thick Film; manufacturer: Panasonic Electronic Components; manufacturer_pn: ERJ-3EKF1002V; id: 182861; value: 10000; Key Parameters: 1% required
R178 = RES-00104: 620 Ohm ±0.1% 0.1W, 1/10W Chip Resistor 0603 (1608 Metric) Automotive AEC-Q200 Thin Film; manufacturer_pn: ERA-3AEB621V; manufacturer: Panasonic Electronic Components; id: 171767; value: 620; Key Parameters: 0.1% required
R179 = RES-00013: as R5 on sheet Peripherals
R180 = RES-00056: 3.4k Ohm ±0.1% 0.1W, 1/10W Chip Resistor 0603 (1608 Metric) Moisture Resistant Thin Film; manufacturer_pn: RT0603BRD073K4L; manufacturer: Yageo; id: 145542; value: 3400; Key Parameters: 0.1% required
R182 = RES-00103: 1.91k Ohm ±0.1% 0.1W, 1/10W Chip Resistor 0603 (1608 Metric) Automotive AEC-Q200 Thin Film; manufacturer_pn: ERA-3AEB1911V; manufacturer: Panasonic Electronic Components; id: 171766; value: 1910; Key Parameters: 0.1% required
R183 R187 R188 R190 R197 = RES-00113: 1 kOhms ±1% 0.1W, 1/10W Chip Resistor 0603 (1608 Metric) Automotive AEC-Q200 Thick Film; manufacturer: Panasonic Electronic Components; manufacturer_pn: ERJ-3EKF1001V; id: 185365; value: 1000; Key Parameters: 1% required
R191 = RES-00055: RES SMD 2.74K OHM 1% 1/10W 0603; manufacturer: Panasonic Electronic Components; manufacturer_pn: ERJ-3EKF2741V; id: 144315; value: 2740; Key Parameters: 1% required
R192 = RES-00050: RES SMD 4.22KOHM 0.1% 1/10W 0603; manufacturer: Yageo; manufacturer_pn: RT0603BRD074K22L; id: 141323; value: 4220; Key Parameters: 0.1% required
TP31 TP32 TP34 TP36-TP39 = NOBOM-00008: Test point, SMD, 1.5mm dia (0.059"); manufacturer: New Horizons; id: 137590
U22 = ICPWR-00039: Linear Voltage Regulator IC Positive Fixed 1 Output 3.3V 200mA SOT-23-5; manufacturer: STMicroelectronics; id: 236192
U23 = ICPWR-00030: Buck Regulator Positive Output Step-Down DC-DC Controller IC 20-HTSSOP; manufacturer: Texas Instruments; id: 171906
U24 = ICANA-00025: Zero-Drift Amplifier 2 Circuit Rail-to-Rail 8-VSSOP; manufacturer_pn: OPA2333AIDGKR; manufacturer: Texas Instruments; id: 172182
U25 = ICPWR-00010: Shunt Voltage Reference IC 24V ±0.25% 100mA SOT-23-3; manufacturer: STMicroelectronics; id: 138487
U29 = ICANA-00028: Series Voltage Reference IC  ±1%  TSOT-23-5; manufacturer: Linear Technology; id: 363943

## Sheet HVAuxMore.SchDoc
size B; SheetNumber: 9; nhSheetName: HV Auxiliary Other
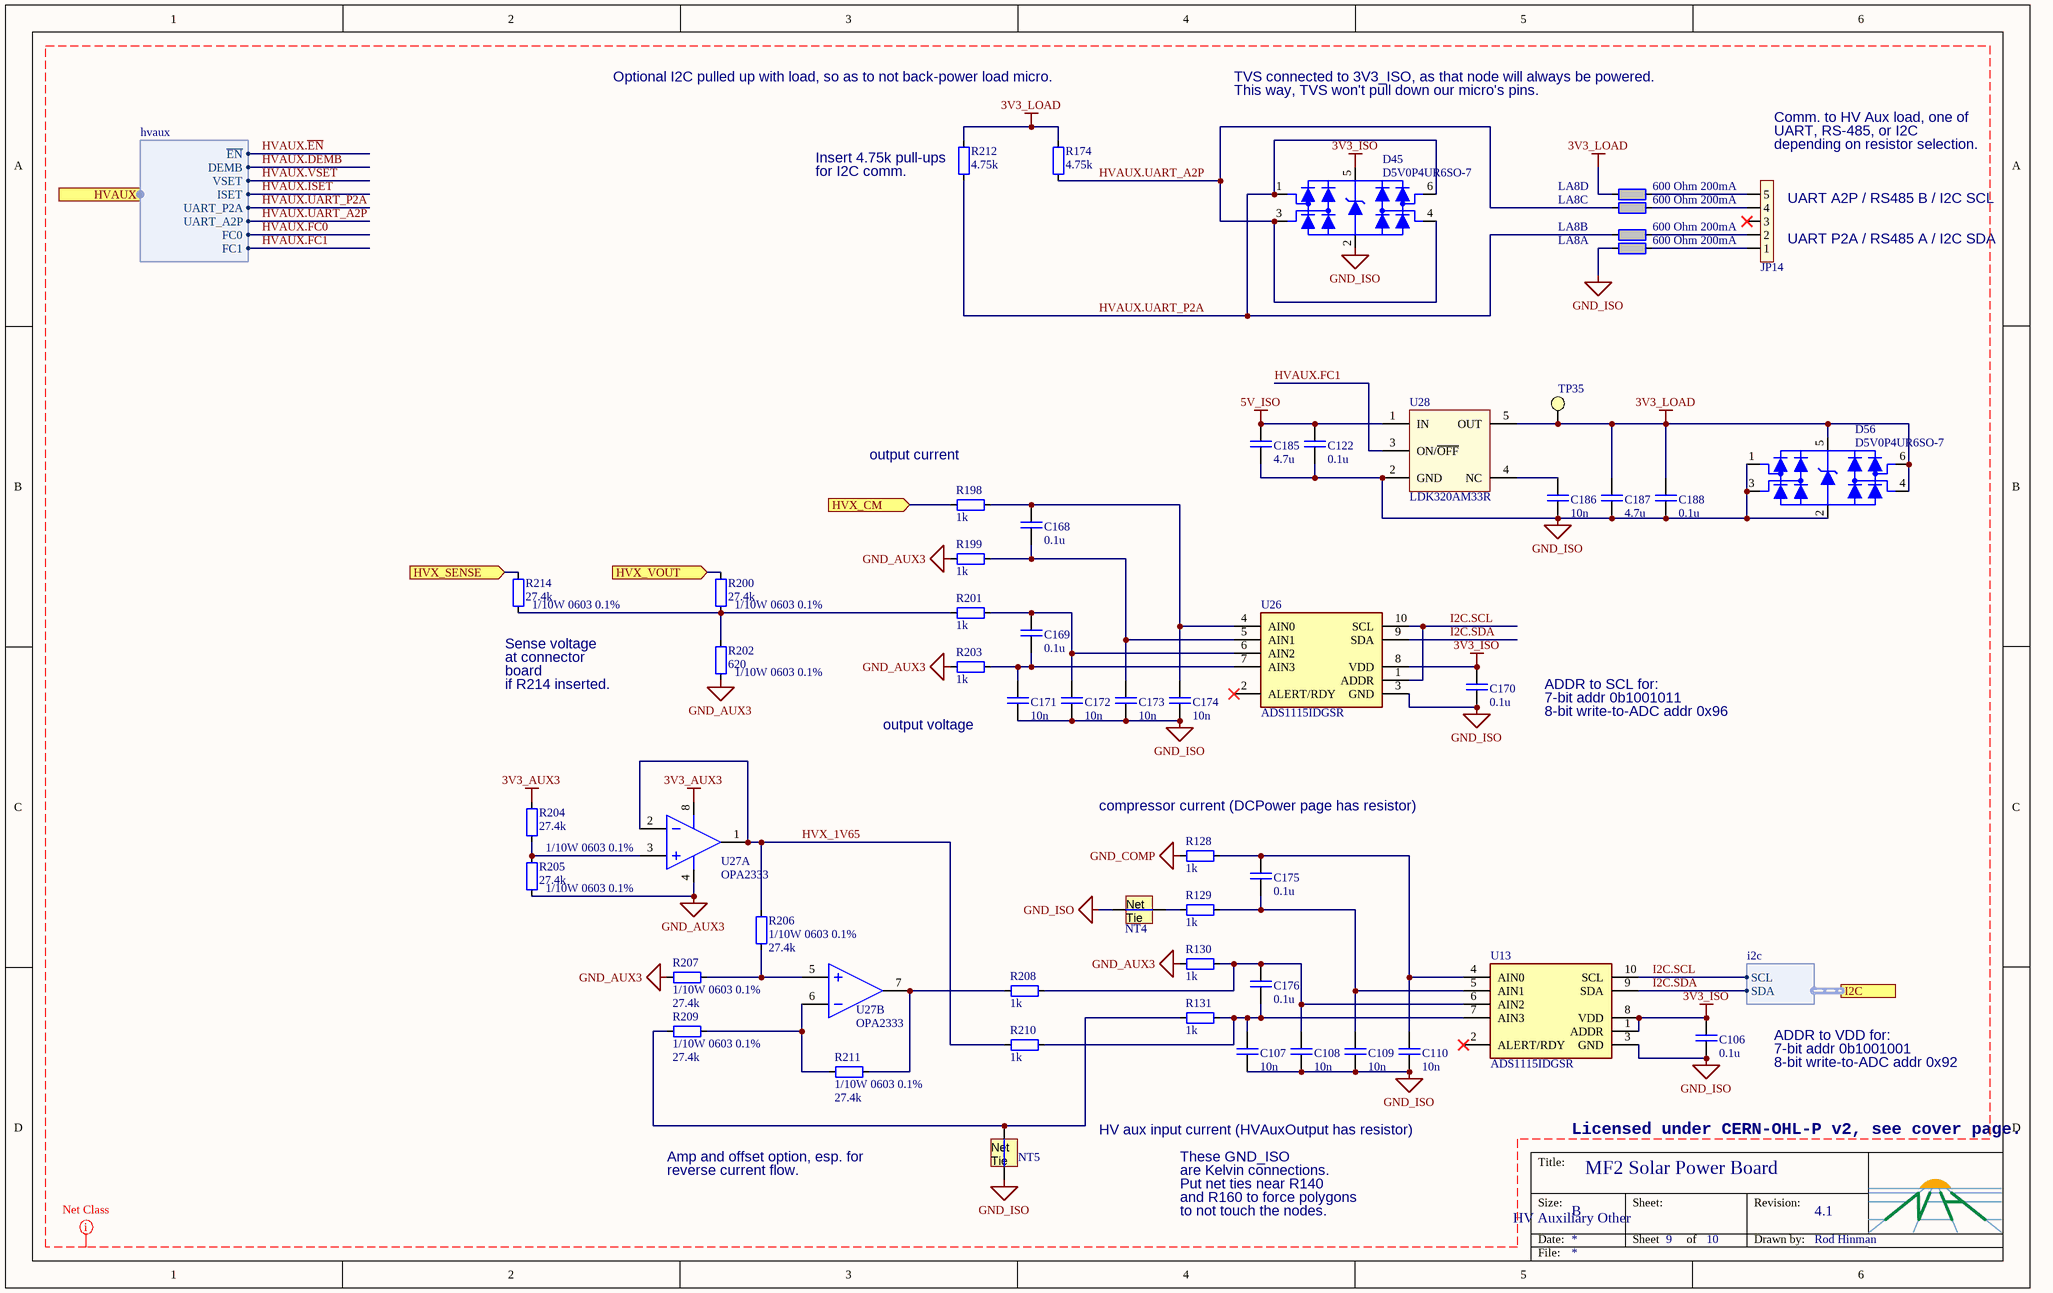
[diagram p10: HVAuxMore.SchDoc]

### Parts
C106  value_text: 0.1u  [CAPC1608X09N[0603]]  (hidden comment: 50V X7R 0603)
C107  value_text: 10n  [CAPC1608X09N[0603]]  (hidden comment: 50V C0G 0603)
C108  value_text: 10n  [CAPC1608X09N[0603]]  (hidden comment: 50V C0G 0603)
C109  value_text: 10n  [CAPC1608X09N[0603]]  (hidden comment: 50V C0G 0603)
C110  value_text: 10n  [CAPC1608X09N[0603]]  (hidden comment: 50V C0G 0603)
C122  value_text: 0.1u  [CAPC1608X09N[0603]]  (hidden comment: 50V X7R 0603)
C168  value_text: 0.1u  [CAPC1608X09N[0603]]  (hidden comment: 50V X7R 0603)
C169  value_text: 0.1u  [CAPC1608X09N[0603]]  (hidden comment: 50V X7R 0603)
C170  value_text: 0.1u  [CAPC1608X09N[0603]]  (hidden comment: 50V X7R 0603)
C171  value_text: 10n  [CAPC1608X09N[0603]]  (hidden comment: 50V C0G 0603)
C172  value_text: 10n  [CAPC1608X09N[0603]]  (hidden comment: 50V C0G 0603)
C173  value_text: 10n  [CAPC1608X09N[0603]]  (hidden comment: 50V C0G 0603)
C174  value_text: 10n  [CAPC1608X09N[0603]]  (hidden comment: 50V C0G 0603)
C175  value_text: 0.1u  [CAPC1608X09N[0603]]  (hidden comment: 50V X7R 0603)
C176  value_text: 0.1u  [CAPC1608X09N[0603]]  (hidden comment: 50V X7R 0603)
C185  value_text: 4.7u  [CAPC1608X09N[0603]]  (hidden comment: 25V X6S 0603)
C186  value_text: 10n  [CAPC1608X09N[0603]]  (hidden comment: 50V C0G 0603)
C187  value_text: 4.7u  [CAPC1608X09N[0603]]  (hidden comment: 25V X6S 0603)
C188  value_text: 0.1u  [CAPC1608X09N[0603]]  (hidden comment: 50V X7R 0603)
D45  manufacturer_pn: D5V0P4UR6SO-7  [SOT23-6]  (hidden comment: TVS)
D56  manufacturer_pn: D5V0P4UR6SO-7  [SOT23-6]  (hidden comment: TVS)
JP14  1x5 2.5mm  [JST_B5B-XH-A(LF)(SN)]  (value not drawn)
LA8  600 Ohm 200mA  [FERCAV80P320X160X70-4]  (parts A,B,C,D of 4)
NT4  Net Tie  [NETTIE_0.254mm_NOPADS]  (value not drawn)  (net tie, no BOM)
NT5  Net Tie  [NETTIE_0.254mm_NOPADS]  (value not drawn)  (net tie, no BOM)
R128  value_text: 1k  [RESC1608X05AN[0603]]  (hidden comment: 1/10W 0603 1%)
R129  value_text: 1k  [RESC1608X05AN[0603]]  (hidden comment: 1/10W 0603 1%)
R130  value_text: 1k  [RESC1608X05AN[0603]]  (hidden comment: 1/10W 0603 1%)
R131  value_text: 1k  [RESC1608X05AN[0603]]  (hidden comment: 1/10W 0603 1%)
R174  value_text: 4.75k  [RESC1608X05AN[0603]]  (hidden comment: 1/10W 0603 1%)
R198  value_text: 1k  [RESC1608X05AN[0603]]  (hidden comment: 1/10W 0603 1%)
R199  value_text: 1k  [RESC1608X05AN[0603]]  (hidden comment: 1/10W 0603 1%)
R200  1/10W 0603 0.1%  value_text: 27.4k  [RESC1608X05AN[0603]]
R201  value_text: 1k  [RESC1608X05AN[0603]]  (hidden comment: 1/10W 0603 1%)
R202  1/10W 0603 0.1%  value_text: 620  [RESC1608X05AN[0603]]
R203  value_text: 1k  [RESC1608X05AN[0603]]  (hidden comment: 1/10W 0603 1%)
R204  1/10W 0603 0.1%  value_text: 27.4k  [RESC1608X05AN[0603]]
R205  1/10W 0603 0.1%  value_text: 27.4k  [RESC1608X05AN[0603]]
R206  1/10W 0603 0.1%  value_text: 27.4k  [RESC1608X05AN[0603]]
R207  1/10W 0603 0.1%  value_text: 27.4k  [RESC1608X05AN[0603]]
R208  value_text: 1k  [RESC1608X05AN[0603]]  (hidden comment: 1/10W 0603 1%)
R209  1/10W 0603 0.1%  value_text: 27.4k  [RESC1608X05AN[0603]]
R210  value_text: 1k  [RESC1608X05AN[0603]]  (hidden comment: 1/10W 0603 1%)
R211  1/10W 0603 0.1%  value_text: 27.4k  [RESC1608X05AN[0603]]
R212  value_text: 4.75k  [RESC1608X05AN[0603]]  (hidden comment: 1/10W 0603 1%)
R214  1/10W 0603 0.1%  value_text: 27.4k  [RESC1608X05AN[0603]]
TP35  TP SMD 1.5mm  [TP_SMD_Ø1.5mm]  (value not drawn)  (no BOM)
U13  manufacturer_pn: ADS1115IDGSR  [TSSOP50P490X110-10N]  (hidden comment: ADS1115)
U26  manufacturer_pn: ADS1115IDGSR  [TSSOP50P490X110-10N]  (hidden comment: ADS1115)
U27  OPA2333  [MSOP-8]  (parts A,B of 2)
U28  manufacturer_pn: LDK320AM33R  [TI-SOT-23-5_MC]  (hidden comment: 3.3V 200mA)

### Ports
HVAUX (harness hvaux), HVX_CM (in), HVX_SENSE (in), HVX_VOUT (in), I2C (harness i2c)

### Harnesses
i2c: SDA, SCL
hvaux: ~{EN}, VSET, UART_P2A, UART_A2P, FC0, FC1, ISET, DEMB

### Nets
3V3_AUX3: R204.1 U27.8(V+)
3V3_ISO: C106.1 C170.1 D45.5(VCC) U13.1(ADDR) U13.8(VDD) U26.8(VDD)
3V3_LOAD: C187.1 C188.1 D56.4(IO3) D56.5(VCC) D56.6(IO4) LA8.5 R174.2 R212.2 TP35.1 U28.5(OUT)
5V_ISO: C122.1 C185.1 U28.1(IN)
GND_AUX3: R130.1 R199.1 R202.2 R203.1 R205.2 R207.1 U27.4(V-)
GND_COMP: R128.1
GND_ISO: C106.2 C107.2 C108.2 C109.2 C110.2 C122.2 C170.2 C171.2 C172.2 C173.2 C174.2 C185.2 C186.2 C187.2 C188.2 D45.2(GND) D56.1(IO1) D56.2(GND) D56.3(IO2) LA8.8 NT4.1 NT5.1 U13.3(GND) U26.3(GND) U28.2(GND)
HVAUX.FC1: U28.3(ON/~{OFF}) ; port HVAUX.FC1
HVAUX.UART_A2P: D45.3(IO2) D45.4(IO3) LA8.6 R174.1 ; port HVAUX.UART_A2P
HVAUX.UART_P2A: D45.1(IO1) D45.6(IO4) LA8.7 R212.1 ; port HVAUX.UART_P2A
HVX_1V65: R206.2 R210.1 U27.1(OUT) U27.2(IN-)
HVX_CM: R198.1 ; port HVX_CM
HVX_VOUT: R200.1 ; port HVX_VOUT
I2C.SCL: U13.10(SCL) U26.1(ADDR) U26.10(SCL) ; port I2C.SCL
I2C.SDA: U13.9(SDA) U26.9(SDA) ; port I2C.SDA
NetC107_1: C107.1 C176.2 R131.2 R210.2 U13.7(AIN3)
NetC108_1: C108.1 C176.1 R130.2 R208.2 U13.6(AIN2)
NetC109_1: C109.1 C175.2 R129.2 U13.5(AIN1)
NetC110_1: C110.1 C175.1 R128.2 U13.4(AIN0)
NetC168_1: C168.1 C174.1 R198.2 U26.4(AIN0)
NetC168_2: C168.2 C173.1 R199.2 U26.5(AIN1)
NetC169_1: C169.1 C172.1 R201.2 U26.6(AIN2)
NetC169_2: C169.2 C171.1 R203.2 U26.7(AIN3)
NetC186_1: C186.1 U28.4(NC)
NetJP14_1: JP14.1 LA8.1
NetJP14_2: JP14.2 LA8.2
NetJP14_4: JP14.4 LA8.3
NetJP14_5: JP14.5 LA8.4
NetL8_1: R214.1 ; port HVX_SENSE
NetNT4_2: NT4.2 R129.1
NetNT5_2: NT5.2 R131.1 R209.1
NetR200_2: R200.2 R201.1 R202.1 R214.2
NetR204_2: R204.2 R205.1 U27.3(IN+)
NetR206_1: R206.1 R207.2 U27.5(IN+)
NetR208_1: R208.1 R211.2 U27.7(OUT)
NetR209_2: R209.2 R211.1 U27.6(IN-)

Not connected (* = marked no-connect by the designer): JP14 3*; U13 2(ALERT/RDY)*; U26 2(ALERT/RDY)*

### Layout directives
net class SELV: 3V3_AUX3, 3V3_ISO, 3V3_LOAD, 5V_ISO, GND_AUX3, GND_COMP, GND_ISO, HVAUX.DEMB, HVAUX.FC0, HVAUX.FC1, HVAUX.ISET, HVAUX.UART_A2P, HVAUX.UART_P2A, HVAUX.VSET, HVAUX.~{EN}, HVX_1V65, I2C.SCL, I2C.SDA

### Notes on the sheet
- Optional I2C pulled up with load, so as to not back-power load micro.
- TVS connected to 3V3_ISO, as that node will always be powered.
- This way, TVS won't pull down our micro's pins.
- (near R212) Insert 4.75k pull-ups
- Comm. to HV Aux load, one of
- UART, RS-485, or I2C
- (near JP14) depending on resistor selection.
- (near R212) for I2C comm.
- (near JP14) UART A2P / RS485 B / I2C SCL
- (near JP14) UART P2A / RS485 A / I2C SDA
- (near R198) output current
- (near R214) Sense voltage
- (near R214) at connector
- board
- if R214 inserted.
- 7-bit addr 0b1001011
- ADDR to SCL for:
- output voltage
- 8-bit write-to-ADC addr 0x96
- compressor current (DCPower page has resistor)
- ADDR to VDD for:
- 7-bit addr 0b1001001
- 8-bit write-to-ADC addr 0x92
- Amp and offset option, esp. for
- reverse current flow.
- HV aux input current (HVAuxOutput has resistor)
- These GND_ISO
- are Kelvin connections.
- Licensed under CERN-OHL-P v2, see cover page.
- Put net ties near R140
- and R160 to force polygons
- to not touch the nodes.

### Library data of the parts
C106 C122 C168-C170 C175 C176 C188 = CAP-00001: as C25 on sheet Peripherals
C107-C110 C171-C174 C186 = CAP-00027: as C144 on sheet HVAuxOutput
C185 C187 = CAP-00015: as C133 on sheet HVAuxOutput
D45 D56 = DIO-00013: TVS DIODE 3.3VWM 6VC SOT26; manufacturer: Diodes Incorporated; id: 140046
JP14 = CONN-00116: 5 Positions Header Connector 0.098" (2.50mm) Through Hole Tin; manufacturer_pn: B5B-XH-A(LF)(SN); manufacturer: JST Sales America Inc.; id: 166570
LA8 = FER-00009: FERRITE BEAD 600 OHM 1206 4LN; manufacturer_pn: BK32164S601-T; manufacturer: Taiyo Yuden; id: 162218; value: 600
NT4 NT5 = NOBOM-00016: Net tie 0.254mm no pads; manufacturer: New Horizons; id: 178547
R128-R131 R198 R199 R201 R203 R208 R210 = RES-00113: 1 kOhms ±1% 0.1W, 1/10W Chip Resistor 0603 (1608 Metric) Automotive AEC-Q200 Thick Film; manufacturer_pn: ERJ-3EKF1001V; manufacturer: Panasonic Electronic Components; id: 185365; value: 1000; Key Parameters: 1% required
R174 R212 = RES-00013: as R5 on sheet Peripherals
R200 R204-R207 R209 R211 R214 = RES-00051: as R176 on sheet HVAuxOutput
R202 = RES-00104: as R178 on sheet HVAuxOutput
TP35 = NOBOM-00008: as TP31 on sheet HVAuxOutput
U13 U26 = ICANA-00023: 16 Bit Analog to Digital Converter 2, 4 Input 1 Sigma-Delta 10-VSSOP; manufacturer: Texas Instruments; id: 169397
U27 = ICANA-00025: as U24 on sheet HVAuxOutput
U28 = ICPWR-00039: as U22 on sheet HVAuxOutput

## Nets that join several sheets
3V3_AUX3: HVAuxOutput (11 pins), HVAuxMore (R204.1 U27.8)
3V3_ISO: Cover (R141.1), DCMonitoring (12 pins), Microcontroller (15 pins), LVPower (5 pins), DCPower (R153.2 R154.2 R157.2), ACPower (6 pins), AuxOutput (C111.1 R86.2 R122.2 U14.8), Peripherals (20 pins), HVAuxOutput (R166.2), HVAuxMore (6 pins)
5V_ISO: Microcontroller (JY6.2 R72.2), LVPower (15 pins), DCPower (D11.5 Q23.2 Q23.5 R87.2), HVAuxMore (C122.1 C185.1 U28.1)
5V_MAIN: Microcontroller (L27.1), LVPower (F4.2)
12V_ISO: DCMonitoring (Q39.2 Q39.5 R142.2), Microcontroller (JY6.4), LVPower (16 pins), HVAuxOutput (D46.A)
12V_MAIN: Microcontroller (L28.2), LVPower (F3.2)
24V: LVPower (D44.A1 D44.A2 R80.2), DCPower (L47.1 Q20.7 Q20.8)
DCBUS: DCPower (6 pins), AuxOutput (8 pins), HVAuxOutput (C136.1 C137.1 C138.1 L2.1)
GND: Cover (Z2.0), DCPower (6 pins), ACPower (7 pins)
GND_AUX3: HVAuxOutput (52 pins), HVAuxMore (7 pins)
GND_COMP: DCPower (L50.1 LA4.1 R140.2), HVAuxMore (R128.1)
GND_ISO: Cover (R152.1), DCMonitoring (44 pins), Microcontroller (22 pins), LVPower (53 pins), DCPower (24 pins), ACPower (9 pins), AuxOutput (11 pins), Peripherals (24 pins), HVAuxOutput (7 pins), HVAuxMore (25 pins)
PVPROT: DCMonitoring (23 pins), LVPower (D43.A1 D43.A2), DCPower (9 pins)
VBAT_UNREG: Microcontroller (LA2.5), LVPower (D2.A)
Vcoil: ACProtection (12 pins), ACPower (K1.PLUS)
COMP.EN: Microcontroller (JY8.2 NT6.1), DCPower (Q9.1 R31.1)
COMP.RX: Microcontroller (JY6.8 U15.64), DCPower (Q12.2 R39.1)
COMP.TX: Microcontroller (JY6.6 U15.63), DCPower (R36.1)
DCMON.N3: DCMonitoring (LA6.1), DCPower (D13.A Q28.S R25.1)
DCMON.N4: DCMonitoring (LA6.2 LA6.3), DCPower (NT1.1)
FAN_ON: Microcontroller (RA5.4), LVPower (Q7.1 R139.1)
FG1: Microcontroller (D26.1 LA1.7 RA5.3), LVPower (C44.1 R79.1)
HVAUX.DEMB: Microcontroller (D10.1 JY6.15 TP14.1 U15.40), HVAuxOutput (Q34.1 R181.2)
HVAUX.~{EN}: Microcontroller (U15.27), HVAuxOutput (Q31.1 R166.1)
HVAUX.FC0: Cover (R141.2 R152.2), Microcontroller (D55.6 JY6.14 RA3.7)
HVAUX.FC1: Microcontroller (D55.4 JY6.16 RA3.8), HVAuxMore (U28.3)
HVAUX.ISET: Microcontroller (U15.39), HVAuxOutput (Q38.1 R196.2)
HVAUX.UART_A2P: Microcontroller (JY6.12 RA5.2), HVAuxMore (D45.3 D45.4 LA8.6 R174.1)
HVAUX.UART_P2A: Microcontroller (JY6.10 RA5.1), HVAuxMore (D45.1 D45.6 LA8.7 R212.1)
HVAUX.VSET: Microcontroller (U15.28), HVAuxOutput (Q36.1 R186.2)
HVX_CM: HVAuxOutput (R191.1 U23.10), HVAuxMore (R198.1)
HVX_VOUT: HVAuxOutput (9 pins), HVAuxMore (R200.1)
I2C.SCL: DCMonitoring (U6.4), Microcontroller (D55.1 JY6.7 U15.18), AuxOutput (U14.10), Peripherals (R5.1 U3.8 U9.1), HVAuxMore (U13.10 U26.1 U26.10)
I2C.SDA: DCMonitoring (U6.5), Microcontroller (D55.3 JY6.5 U15.17), AuxOutput (U14.9), Peripherals (R6.1 U3.7 U9.3), HVAuxMore (U13.9 U26.9)
MON.ADC_CLK: DCMonitoring (U4.13), Microcontroller (RA2.2), ACPower (U8.13)
MON.~{CS}_MAINS: Microcontroller (RA3.6), ACPower (U8.18)
MON.~{CS}_PV: DCMonitoring (U4.18), Microcontroller (RA1.6)
MON.CAL: DCMonitoring (Q11.1 TP18.1), Microcontroller (U15.6)
MON.~{DR}_PV: DCMonitoring (U4.12), Microcontroller (RA3.5)
MON.MISO: DCMonitoring (U4.15), Microcontroller (R17.2 RA1.5), ACPower (U8.15)
MON.MOSI: DCMonitoring (U4.16), Microcontroller (RA1.7), ACPower (U8.16)
MON.MOV_BAD: Microcontroller (U15.62), ACPower (C43.1 R81.2 U7.4)
MON.SCLK: DCMonitoring (U4.17), Microcontroller (RA1.8), ACPower (U8.17)
NetL8_1: HVAuxOutput (L8.1 R213.1), HVAuxMore (R214.1)
PROT.LFUSED: ACProtection (C31.1 R91.1 R92.1), ACPower (5 pins)
PROT.NPROT: ACProtection (D15.K D39.A), ACPower (10 pins)
PROT.RESET: ACProtection (D21.A Q17.3), ACPower (K1.RESET)
PROT.SET: ACProtection (D20.A Q16.3), ACPower (K1.SET)
PWR_AVAIL.BIT0: DCMonitoring (R20.1 U1.3), Microcontroller (U15.20)
PWR_AVAIL.BIT1: DCMonitoring (R21.1 U1.5), Microcontroller (U15.2)
PWR_AVAIL.BIT2: DCMonitoring (R22.2 U1.7), Microcontroller (U15.11)
PWR_AVAIL.BIT3: DCMonitoring (R30.1 U1.9), Microcontroller (U15.12)
PWR_AVAIL.BIT4: DCMonitoring (R33.1 U1.11), Microcontroller (U15.51)
PWR_AVAIL.BIT5: DCMonitoring (R35.2 U1.14), Microcontroller (U15.53)
PWR_SEL.5VAUX_~{EN}: Microcontroller (RA4.8), AuxOutput (Q19.1 R122.1)
PWR_SEL.12VAUX_~{EN}: Microcontroller (RA4.7), AuxOutput (Q18.1 R86.1)
PWR_SEL.COMP_PWRD: Microcontroller (U15.61), DCPower (Q24.1 Q25.1 R98.1 R156.2)
PWR_SEL.MAINBRD_EN: DCMonitoring (R144.1), Microcontroller (U15.19), LVPower (Q10.1 Q22.1 R1.1 R47.2)
PWR_SEL.SEL_AC: Microcontroller (TP29.1 U15.60), DCPower (Q14.1 R155.2)
PWR_SEL.SEL_PV: Microcontroller (TP28.1 U15.59), DCPower (Q29.1 R158.2)
RTC_INT: Microcontroller (U15.49), Peripherals (R8.1 U3.3)

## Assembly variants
As Built: not fitted C30 C41 C144 C186 JY1 JY2 JY5 JY6 JY8 L10 L34 MECH1 MECH2 MECH3 MECH4 MECH5 MECH6 R93 R94 R95 R96 R174 R208 R210 R212 R213 R214 R215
